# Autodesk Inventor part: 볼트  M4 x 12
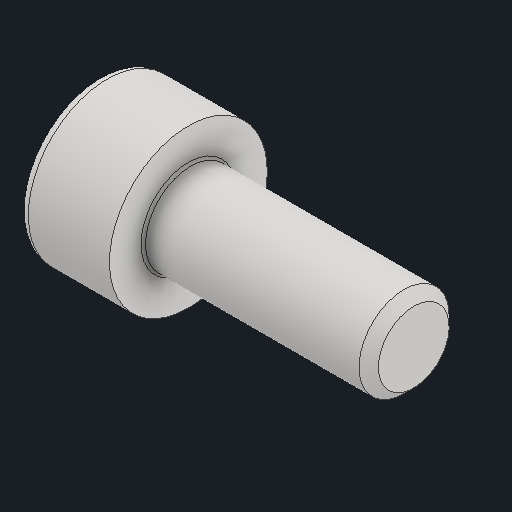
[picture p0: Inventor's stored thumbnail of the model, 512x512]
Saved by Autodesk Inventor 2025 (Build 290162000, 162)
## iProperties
Created: 2025-08
Part Number: 볼트  M4 x 12
Material: 스테인리스강
Description: 6각머리 태핑 나사
Document SubType Name: Modeling
Designer: infra005
Density: 8.08 g/cm^3
Appearance: 기본값
Author: jhkim
Sending System: Autodesk Inventor 2026
Preprocessor: ST-DEVELOPER v20.1
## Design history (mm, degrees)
feature "Solid1"
node "솔리드1"
